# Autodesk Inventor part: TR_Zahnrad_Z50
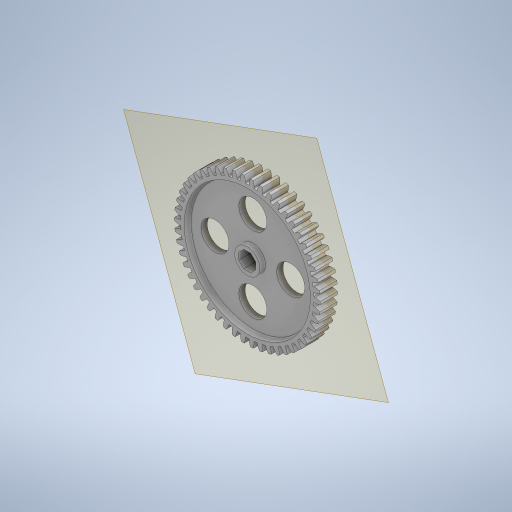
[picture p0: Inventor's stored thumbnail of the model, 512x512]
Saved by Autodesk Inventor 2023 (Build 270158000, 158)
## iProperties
Created: 2023-11
Part Number: TR_Zahnrad_Z50
Material: Generic
Document SubType Name: Modeling
Designer: AdminForWorker
Density: 1 g/cm^3
Appearance: Default
Title: Component1
Author: AdminForWorker
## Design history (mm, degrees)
feature "Body1"
workplane "Arbeitsebene1"
sketch "Skizze1"
  geometry: C1 r 22 at (-23.28, 9.411); C2 r 4.5 at (-23.28, 9.411); 1 further point
  constraints: 2 centre point, 2 coincident
  dimensions: "d0" = 44 diameter of C1; "d1" = 9 diameter of C2
extrude "Extrusion1" cut sketch "Skizze1" distance "d2" = 2; taper "d3" = 0 deg
mirror "Spiegeln2"
chamfer "Fase2" distance "d7" = 0.5; stored, may be unused: second distance "d8" = 2, angle "d9" = 45 deg
chamfer "Fase3" distance "d10" = 0.5; stored, may be unused: second distance "d11" = 2, angle "d12" = 45 deg
sketch "Skizze2"
  geometry: C1 r 5 at (0, 13.5); 1 further point
  constraints: 1 centre point, 1 vertical alignment
  dimensions: "d13" = 10 diameter of C1; "d14" = 13.5 distance of point (0, 0) C1.centre
extrude "Extrusion2" cut sketch "Skizze2" extent not by distance; stored distance "d15" = 0; taper "d16" = 0 deg
pattern_circular "Runde Anordnung1" dims angle "d18" = 360 deg
sketch "Skizze3"
  geometry: L1 (1.243, 3)-(3, 1.243); L2 (3, 1.243)-(3, -1.243); L3 (3, -1.243)-(1.243, -3); L4 (1.243, -3)-(-1.243, -3); L5 (-1.243, -3)-(-3, -1.243); L6 (-3, -1.243)-(-3, 1.243); L7 (-3, 1.243)-(-1.243, 3); L8 (-1.243, 3)-(1.243, 3); 2 further points
  constraints: 16 end point, 1 coincident, 1 horizontal, 17 other
  dimensions: "d20" = 6 distance between parallel lines of L2 L6 (= AchteckUmkreis)
extrude "Extrusion3" cut sketch "Skizze3" extent not by distance; stored distance "d21" = 0; taper "d22" = 0 deg
body "Solid1"
other parameters: "Radius" = 2.075 [user parameter], "Fasen" = 0.5 [user parameter], "Dicke" = 0.8 [user parameter], "Breitloch" = 2 [user parameter], "Langloch" = 32 [user parameter], "AchteckUmkreis" = 6 [user parameter; used in 1 equation term], "DAchsAufnahme" = 4.1 [user parameter], "AchsDurchmesser" = 4 [user parameter], "AchsFase" = 0.5 [user parameter]
